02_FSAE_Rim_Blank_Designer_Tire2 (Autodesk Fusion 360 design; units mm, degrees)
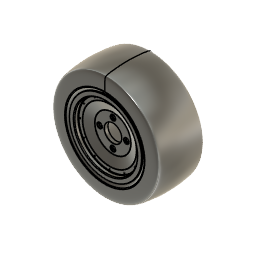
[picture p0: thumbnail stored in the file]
part number: 2026-07-27-09-56-27-671
sketch "Sketch1" plane through (0, 0, 0) normal (1, 0, 0) x axis (0, 1, 0)
  line L1 (153.5, 0) -> (0, 0)
  line L2 (0, 119.5) -> (0, 104)
  line L3 (143.5, 124.5) -> (5, 124.5)
  line L4 (148.5, 134.75) -> (148.5, 129.5)
  line L5 (153.5, 138.25) -> (152, 138.25)
  line L6 (2.5, 119.5) -> (2.5, 104)
  line L7 (143.5, 122) -> (5, 122)
  line L8 (151, 134.75) -> (151, 129.5)
  line L9 (153.5, 135.75) -> (152, 135.75)
  line L10 (2.5, 104) -> (0, 104)
  line L11 (153.5, 135.75) -> (153.5, 138.25)
  arc A1 centre (152, 134.75) radius 3.5 clockwise from (148.5, 134.75) to (152, 138.25)
  arc A2 centre (143.5, 129.5) radius 5 clockwise from (148.5, 129.5) to (143.5, 124.5)
  arc A3 centre (5, 119.5) radius 5 clockwise from (0, 119.5) to (5, 124.5)
  arc A4 centre (5, 119.5) radius 2.5 clockwise from (2.5, 119.5) to (5, 122)
  arc A5 centre (143.5, 129.5) radius 7.5 clockwise from (151, 129.5) to (143.5, 122)
  arc A6 centre (152, 134.75) radius 1 clockwise from (151, 134.75) to (152, 135.75)
  point P1 (0, 0)
  point P2 (0, 0)
  point P4 (0, 104)
  point P3 (153.5, 0)
  point P7 (153.5, 138.25)
  point P6 (148.5, 124.5)
  point P5 (0, 124.5)
  coincident P1 P2
  horizontal L1
  perpendicular L1 L2
  perpendicular L2 L3
  perpendicular L3 L4
  perpendicular L4 L5
  vertical P1 P4
  vertical P3 P7
  tangent L4 A1
  tangent L5 A1
  coincident P6 L3
  coincident P6 L4
  tangent L3 A2
  tangent L4 A2
  coincident P5 L2
  coincident P5 L3
  tangent L2 A3
  tangent L3 A3
  equal A2 A3
  perpendicular L6 L10
  perpendicular L9 L11
  dimension "d1" distance P2 P3 = 153.5
  dimension "d2" = 208
  dimension "d3" = 249
  dimension "d4" = 276.5
  dimension "d5" distance P5 P6 = 148.5
  dimension "d6" radius A1 = 3.5
  dimension "d7" radius A2 = 5
  dimension "d8" = 2.5
revolve "Revolve1" sketch "Sketch1" AlongAngle 360 bodies "FSAE Rim Back"
sketch "Sketch2" plane through (0, 0, 0) normal (0, -1, 0) x axis (1, 0, 0)
  circle C1 centre (0, 0) radius 104
  circle C2 centre (0, 0) radius 119.5
  circle C3 centre (0, 0) radius 112
  circle C4 centre (0, 112) radius 2.15
  point P1 (0, 0)
  point P3 (0, 0)
  point P4 (0, 112)
  coincident P1 P3
  coincident C3 P4
  vertical P3 P4
  dimension "d10" diameter C3 = 224
  dimension "d11" diameter C4 = 4.3
extrude "Extrude1" cut sketch "Sketch2" profile of C4 to an object
circular_pattern "C-Pattern1" TotalAngle 360
canvas "Canvas1"
move "Move1"
sketch "Sketch4" plane through (0, 0, 0) normal (1, 0, 0) x axis (0, 1, 0)
  line L1 (14, 0) -> (0, 0)
  line L2 (14, 72.5) -> (14, 0)
  line L3 (-8, 102.5) -> (14, 72.5)
  line L4 (-8, 124.5) -> (-8, 102.5)
  line L5 (-23.5, 124.5) -> (-8, 124.5)
  line L6 (-23.5, 138) -> (-23.5, 124.5)
  line L7 (-28.25, 138) -> (-23.5, 138)
  line L8 (-28.25, 0) -> (-28.25, 138)
  line L9 (0, 0) -> (-28.25, 0)
  line L10 (-13, 118.1658) -> (-28.25, 119.5)
  line L11 (-13, 102.5) -> (-13, 118.1658)
  line L12 (0, 68.6338) -> (-13, 102.5)
  line L13 (0, 0) -> (0, 68.6338)
  point P1 (0, 0)
  point P2 (0, 0)
  point P11 (0, 0)
  point P12 (-28.25, 119.5)
  point P5 (-8, 102.5)
  point P14 (-13, 102.5)
  point P3 (14, 0)
  point P4 (14, 72.5)
  point P6 (-8, 124.5)
  point P8 (-23.5, 138)
  point P9 (-28.25, 138)
  coincident P1 P2
  horizontal L1
  perpendicular L1 L2
  perpendicular L1 L4
  perpendicular L4 L5
  perpendicular L5 L6
  perpendicular L6 L7
  coincident P1 P11
  collinear L1 L9
  perpendicular L8 L9
  coincident L8 P12
  parallel L8 L11
  vertical L13
  horizontal P5 P14
  dimension "d29" distance P2 P3 = 14
  dimension "d30" = 145
  dimension "d31" = 205
  dimension "d32" = 249
  dimension "d33" = 276
  dimension "d34" distance P4 P6 = 22
  dimension "d35" distance P6 P8 = 15.5
  dimension "d36" distance P8 P9 = 4.75
  dimension "d37" distance L4 L11 = 5
  dimension "d38" angle L12 L13 = 159
  dimension "d39" angle L10 L11 = 95
  dimension "d40" = 239
revolve "Revolve3" sketch "Sketch4" AlongAngle 360 bodies "FSAE Rim Front"
sketch "Sketch5" plane through (0, 0, 0) normal (0, -1, 0) x axis (1, 0, 0)
  circle C1 centre (0, 0) radius 68.6338
  circle C2 centre (0, 0) radius 33
  point P1 (0, 0)
  point P3 (0, 0)
  coincident P1 P3
  dimension "d42" diameter C2 = 66
extrude "Extrude2" cut sketch "Sketch5" profile of C2 to an object
sketch "Sketch6" plane through (0, 0, 0) normal (0, -1, 0) x axis (1, 0, 0)
  circle C1 centre (0, 0) radius 33
  circle C2 centre (0, 0) radius 68.6338
  circle C3 centre (0, 0) radius 50.8
  point P1 (0, 0)
  point P4 (0, 0)
  point P3 (0, 50.8)
  coincident P1 P4
  coincident P3 C3
  vertical P1 P3
  dimension "d45" diameter C3 = 101.6
hole "Hole1" HoleDiameter 10.5 TipAngle 180 CBDepth 5 CBDiameter 20
chamfer "Chamfer2" sketch "Sketch1" distance 0.5
circular_pattern "C-Pattern2" TotalAngle 360
sketch "Sketch7" plane through (0, -13, 0) normal (0, -1, 0) x axis (1, 0, 0)
  circle C1 centre (0, 0) radius 102.5
  circle C2 centre (0, 0) radius 118.1658
  circle C3 centre (0, 0) radius 112
  point P1 (0, 0)
  point P3 (0, 0)
  point P4 (0, 112)
  coincident P1 P3
  coincident C3 P4
  vertical P1 P4
  dimension "d53" diameter C3 = 224
hole "Hole2" HoleDiameter 4.3 TipAngle 180
circular_pattern "C-Pattern3" TotalAngle 360
fillet "Fillet1" radius 1 3 2
chamfer "Chamfer1" distance 0.5
form "Form1"
fillet "Fillet2" radius 5
named bodies: "FSAE Rim Back", "FSAE Rim Front"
